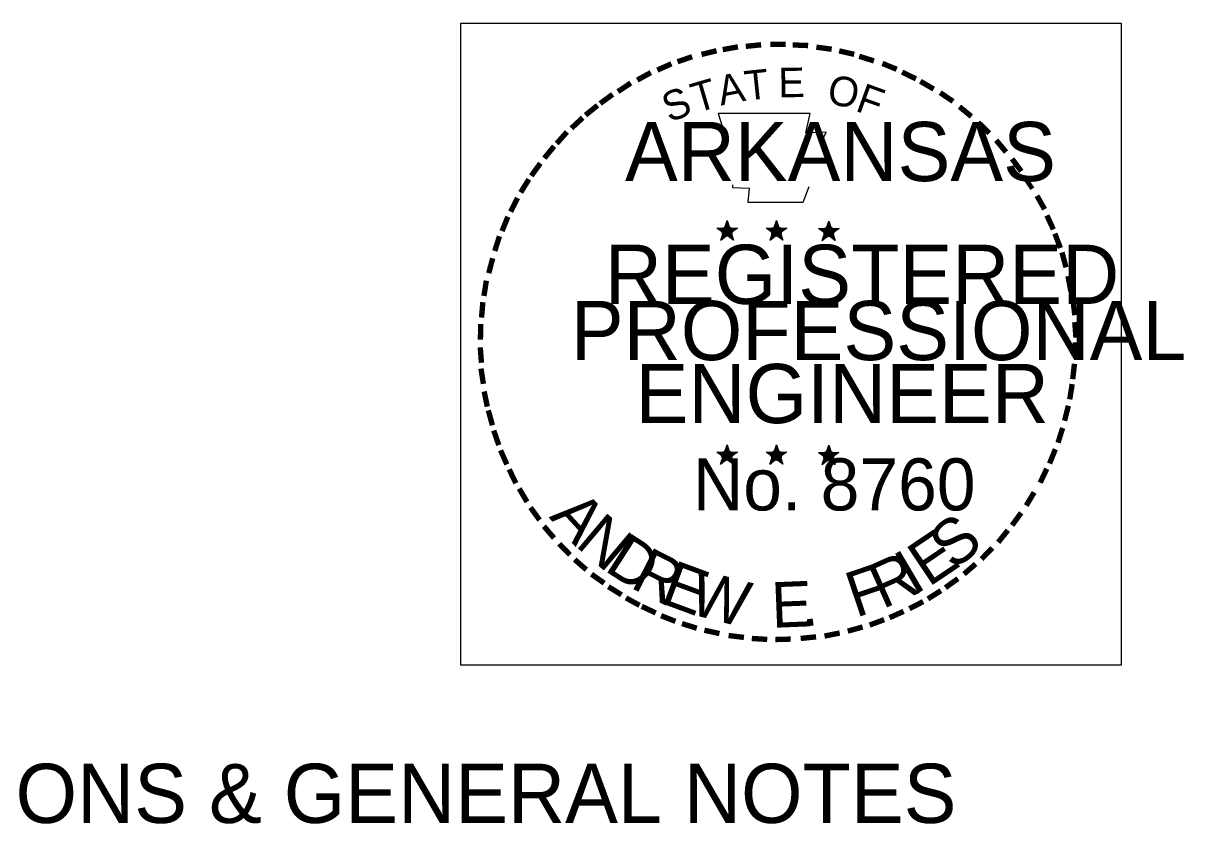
# Model space of a CAD drawing. Extents: x 1226673 to 1228148, y 151313 to 152324.
# Drawn here: x 1227902.7 to 1228147.9, y 151312.6 to 151481.8 of the extents above; entities that cross this region are included whole.
import ezdxf

# ---------------------------------------------------------------- set-up
doc = ezdxf.new("R2010")
doc.units = 0
for name, color, linetype in [('R_Border Notes', 7, 'Continuous'), ('R_Border PE', 7, 'Continuous'), ('R_Border Prem', 7, 'Continuous')]:
    doc.layers.add(name, color=color, linetype=linetype)

msp = doc.modelspace()

# ---------------------------------------------------------------- linework, layer by layer
at = {"layer": 'R_Border PE'}
for p, q in [((1228051.43, 151440.09), (1228051.11, 151438.53)), ((1228051.43, 151440.09), (1228051.18, 151438.47)), ((1228051.43, 151440.09), (1228051.36, 151438.53)), ((1228051.43, 151437.78), (1228051.43, 151440.09)), ((1228051.43, 151440.09), (1228051.86, 151438.47)), ((1228051.43, 151440.09), (1228051.74, 151438.53)), ((1228051.43, 151440.09), (1228051.61, 151438.53)), ((1228061.86, 151440.09), (1228061.55, 151438.53)), ((1228061.86, 151440.09), (1228061.61, 151438.47)), ((1228061.86, 151440.09), (1228061.74, 151438.53)), ((1228061.86, 151437.78), (1228061.86, 151440.09)), ((1228061.86, 151440.09), (1228062.3, 151438.47)), ((1228061.86, 151440.09), (1228062.18, 151438.53)), ((1228061.86, 151440.09), (1228061.99, 151438.53)), ((1228072.93, 151439.97), (1228072.55, 151438.47)), ((1228072.93, 151439.97), (1228072.68, 151438.41)), ((1228072.93, 151439.97), (1228072.8, 151438.41)), ((1228072.93, 151437.72), (1228072.93, 151439.97)), ((1228072.93, 151439.97), (1228073.36, 151438.41)), ((1228072.93, 151439.97), (1228073.24, 151438.41)), ((1228072.93, 151439.97), (1228073.05, 151438.47)), ((1228049.24, 151438.47), (1228051.43, 151437.78)), ((1228049.24, 151438.47), (1228050.86, 151438.34)), ((1228049.24, 151438.47), (1228050.86, 151438.22)), ((1228049.24, 151438.47), (1228050.8, 151438.09)), ((1228049.24, 151438.47), (1228050.8, 151437.84)), ((1228049.24, 151438.47), (1228050.74, 151437.72)), ((1228049.24, 151438.47), (1228050.74, 151437.59)), ((1228050.11, 151435.91), (1228051.43, 151437.78)), ((1228050.11, 151435.91), (1228050.8, 151437.66)), ((1228050.11, 151435.91), (1228050.86, 151437.47)), ((1228050.11, 151435.91), (1228050.99, 151437.41)), ((1228050.11, 151435.91), (1228051.43, 151437.28)), ((1228050.11, 151435.91), (1228051.18, 151437.22)), ((1228050.11, 151435.91), (1228051.49, 151437.09)), ((1228053.61, 151438.47), (1228051.43, 151437.78)), ((1228052.8, 151435.91), (1228051.43, 151437.78)), ((1228052.8, 151435.91), (1228051.43, 151437.28)), ((1228052.8, 151435.91), (1228051.43, 151437.09)), ((1228053.61, 151438.47), (1228051.68, 151438.34)), ((1228052.8, 151435.91), (1228051.68, 151437.22)), ((1228053.61, 151438.47), (1228051.8, 151438.16)), ((1228053.61, 151438.47), (1228051.8, 151438.03)), ((1228052.8, 151435.91), (1228051.86, 151437.47)), ((1228052.8, 151435.91), (1228051.93, 151437.72)), ((1228052.8, 151435.91), (1228052.05, 151437.78)), ((1228053.61, 151438.47), (1228052.24, 151437.91)), ((1228053.61, 151438.47), (1228052.36, 151437.84)), ((1228053.61, 151438.47), (1228052.43, 151437.78)), ((1228059.68, 151438.47), (1228061.86, 151437.78)), ((1228059.68, 151438.47), (1228061.3, 151438.34)), ((1228059.68, 151438.47), (1228061.3, 151438.22)), ((1228059.68, 151438.47), (1228061.24, 151438.09)), ((1228059.68, 151438.47), (1228061.18, 151437.84)), ((1228059.68, 151438.47), (1228061.18, 151437.72)), ((1228059.68, 151438.47), (1228061.18, 151437.59)), ((1228060.55, 151435.91), (1228061.86, 151437.78)), ((1228060.55, 151435.91), (1228061.24, 151437.66)), ((1228060.55, 151435.91), (1228061.3, 151437.47)), ((1228060.55, 151435.91), (1228061.43, 151437.41)), ((1228060.55, 151435.91), (1228061.86, 151437.28)), ((1228060.55, 151435.91), (1228061.61, 151437.22)), ((1228060.55, 151435.91), (1228061.93, 151437.09)), ((1228064.05, 151438.47), (1228061.86, 151437.78)), ((1228063.24, 151435.91), (1228061.86, 151437.78)), ((1228063.24, 151435.91), (1228061.86, 151437.28)), ((1228063.24, 151435.91), (1228061.86, 151437.09)), ((1228064.05, 151438.47), (1228062.11, 151438.34)), ((1228063.24, 151435.91), (1228062.11, 151437.22)), ((1228064.05, 151438.47), (1228062.24, 151438.16)), ((1228064.05, 151438.47), (1228062.24, 151438.03)), ((1228063.24, 151435.91), (1228062.3, 151437.47)), ((1228063.24, 151435.91), (1228062.36, 151437.72)), ((1228063.24, 151435.91), (1228062.49, 151437.78)), ((1228064.05, 151438.47), (1228062.68, 151437.91)), ((1228064.05, 151438.47), (1228062.8, 151437.84)), ((1228064.05, 151438.47), (1228062.86, 151437.78)), ((1228070.74, 151438.41), (1228072.93, 151437.72)), ((1228070.74, 151438.41), (1228072.36, 151438.22)), ((1228070.74, 151438.41), (1228072.3, 151438.09)), ((1228070.74, 151438.41), (1228072.3, 151438.03)), ((1228070.74, 151438.41), (1228072.24, 151437.78)), ((1228070.74, 151438.41), (1228072.24, 151437.66)), ((1228070.74, 151438.41), (1228072.24, 151437.53)), ((1228071.55, 151435.84), (1228072.93, 151437.72)), ((1228071.55, 151435.84), (1228072.3, 151437.59)), ((1228071.55, 151435.84), (1228072.36, 151437.41)), ((1228071.55, 151435.84), (1228072.49, 151437.34)), ((1228071.55, 151435.84), (1228072.93, 151437.22)), ((1228071.55, 151435.84), (1228072.68, 151437.16)), ((1228071.55, 151435.84), (1228072.99, 151437.03)), ((1228075.11, 151438.41), (1228072.93, 151437.72)), ((1228074.24, 151435.84), (1228072.93, 151437.72)), ((1228074.24, 151435.84), (1228072.93, 151437.22)), ((1228074.24, 151435.84), (1228072.93, 151437.03)), ((1228075.11, 151438.41), (1228073.18, 151438.28)), ((1228074.24, 151435.84), (1228073.18, 151437.16)), ((1228075.11, 151438.41), (1228073.3, 151438.09)), ((1228075.11, 151438.41), (1228073.3, 151437.97)), ((1228074.24, 151435.84), (1228073.36, 151437.41)), ((1228074.24, 151435.84), (1228073.43, 151437.66)), ((1228074.24, 151435.84), (1228073.55, 151437.66)), ((1228075.11, 151438.41), (1228073.74, 151437.84)), ((1228075.11, 151438.41), (1228073.8, 151437.78)), ((1228075.11, 151438.41), (1228073.93, 151437.72)), ((1228051.43, 151392.72), (1228051.05, 151391.22)), ((1228051.43, 151392.72), (1228051.18, 151391.16)), ((1228051.43, 151392.72), (1228051.3, 151391.16)), ((1228051.43, 151390.47), (1228051.43, 151392.72)), ((1228051.43, 151392.72), (1228051.86, 151391.16)), ((1228051.43, 151392.72), (1228051.74, 151391.16)), ((1228051.43, 151392.72), (1228051.55, 151391.16)), ((1228061.86, 151392.72), (1228061.49, 151391.22)), ((1228061.86, 151392.72), (1228061.61, 151391.16)), ((1228061.86, 151392.72), (1228061.74, 151391.16)), ((1228061.86, 151390.47), (1228061.86, 151392.72)), ((1228061.86, 151392.72), (1228062.24, 151391.16)), ((1228061.86, 151392.72), (1228062.18, 151391.16)), ((1228061.86, 151392.72), (1228061.99, 151391.16)), ((1228072.93, 151392.66), (1228072.55, 151391.09)), ((1228072.93, 151392.66), (1228072.68, 151391.09)), ((1228072.93, 151392.66), (1228072.8, 151391.09)), ((1228072.93, 151390.41), (1228072.93, 151392.66)), ((1228072.93, 151392.66), (1228073.3, 151391.09)), ((1228072.93, 151392.66), (1228073.24, 151391.09)), ((1228072.93, 151392.66), (1228073.05, 151391.09)), ((1228049.24, 151391.16), (1228051.43, 151390.47)), ((1228049.24, 151391.16), (1228050.86, 151390.97)), ((1228049.24, 151391.16), (1228050.8, 151390.84)), ((1228049.24, 151391.16), (1228050.8, 151390.78)), ((1228049.24, 151391.16), (1228050.74, 151390.53)), ((1228049.24, 151391.16), (1228050.74, 151390.41)), ((1228049.24, 151391.16), (1228050.74, 151390.28)), ((1228050.05, 151388.59), (1228051.43, 151390.47)), ((1228050.05, 151388.59), (1228050.8, 151390.34)), ((1228053.61, 151391.16), (1228051.43, 151390.47)), ((1228052.74, 151388.59), (1228051.43, 151390.47)), ((1228053.61, 151391.16), (1228051.68, 151391.03)), ((1228053.61, 151391.16), (1228051.8, 151390.84)), ((1228053.61, 151391.16), (1228051.8, 151390.72)), ((1228052.74, 151388.59), (1228051.86, 151390.41)), ((1228052.74, 151388.59), (1228052.05, 151390.41)), ((1228053.61, 151391.16), (1228052.18, 151390.59)), ((1228053.61, 151391.16), (1228052.3, 151390.53)), ((1228053.61, 151391.16), (1228052.43, 151390.41)), ((1228059.68, 151391.16), (1228061.86, 151390.47)), ((1228059.68, 151391.16), (1228061.24, 151390.97)), ((1228059.68, 151391.16), (1228061.24, 151390.84)), ((1228059.68, 151391.16), (1228061.24, 151390.78)), ((1228059.68, 151391.16), (1228061.18, 151390.53)), ((1228059.68, 151391.16), (1228061.18, 151390.41)), ((1228059.68, 151391.16), (1228061.18, 151390.28)), ((1228060.49, 151388.59), (1228061.86, 151390.47)), ((1228060.49, 151388.59), (1228061.24, 151390.34)), ((1228063.99, 151391.16), (1228061.86, 151390.47)), ((1228063.18, 151388.59), (1228061.86, 151390.47)), ((1228063.99, 151391.16), (1228062.11, 151391.03)), ((1228063.99, 151391.16), (1228062.24, 151390.84)), ((1228063.99, 151391.16), (1228062.24, 151390.72)), ((1228063.18, 151388.59), (1228062.3, 151390.41)), ((1228063.18, 151388.59), (1228062.49, 151390.41)), ((1228063.99, 151391.16), (1228062.61, 151390.59)), ((1228063.99, 151391.16), (1228062.74, 151390.53)), ((1228063.99, 151391.16), (1228062.86, 151390.41)), ((1228070.74, 151391.09), (1228072.93, 151390.41)), ((1228070.74, 151391.09), (1228072.3, 151390.91)), ((1228070.74, 151391.09), (1228072.3, 151390.78)), ((1228070.74, 151391.09), (1228072.24, 151390.66)), ((1228070.74, 151391.09), (1228072.24, 151390.47)), ((1228070.74, 151391.09), (1228072.18, 151390.28)), ((1228070.74, 151391.09), (1228072.18, 151390.16)), ((1228071.55, 151388.53), (1228072.93, 151390.41)), ((1228071.55, 151388.53), (1228072.24, 151390.28)), ((1228075.05, 151391.09), (1228072.93, 151390.41)), ((1228074.24, 151388.53), (1228072.93, 151390.41)), ((1228075.05, 151391.09), (1228073.18, 151390.97)), ((1228075.05, 151391.09), (1228073.3, 151390.78)), ((1228075.05, 151391.09), (1228073.3, 151390.66)), ((1228074.24, 151388.53), (1228073.36, 151390.34)), ((1228074.24, 151388.53), (1228073.49, 151390.34)), ((1228075.05, 151391.09), (1228073.68, 151390.53)), ((1228075.05, 151391.09), (1228073.8, 151390.41)), ((1228075.05, 151391.09), (1228073.86, 151390.34)), ((1228050.05, 151388.59), (1228050.86, 151390.09)), ((1228050.05, 151388.59), (1228050.99, 151390.03)), ((1228050.05, 151388.59), (1228051.43, 151389.97)), ((1228050.05, 151388.59), (1228051.18, 151389.91)), ((1228050.05, 151388.59), (1228051.43, 151389.78)), ((1228052.74, 151388.59), (1228051.36, 151389.78)), ((1228052.74, 151388.59), (1228051.43, 151389.91)), ((1228052.74, 151388.59), (1228051.61, 151389.91)), ((1228052.74, 151388.59), (1228051.86, 151390.16)), ((1228060.49, 151388.59), (1228061.3, 151390.09)), ((1228060.49, 151388.59), (1228061.43, 151390.03)), ((1228060.49, 151388.59), (1228061.86, 151389.97)), ((1228060.49, 151388.59), (1228061.61, 151389.91)), ((1228060.49, 151388.59), (1228061.86, 151389.78)), ((1228063.18, 151388.59), (1228061.8, 151389.78)), ((1228063.18, 151388.59), (1228061.86, 151389.91)), ((1228063.18, 151388.59), (1228062.05, 151389.91)), ((1228063.18, 151388.59), (1228062.3, 151390.16)), ((1228071.55, 151388.53), (1228072.3, 151390.03)), ((1228071.55, 151388.53), (1228072.49, 151389.97)), ((1228071.55, 151388.53), (1228072.68, 151389.84)), ((1228071.55, 151388.53), (1228072.86, 151389.84)), ((1228071.55, 151388.53), (1228072.93, 151389.72)), ((1228074.24, 151388.53), (1228072.86, 151389.84)), ((1228074.24, 151388.53), (1228072.86, 151389.66)), ((1228074.24, 151388.53), (1228073.11, 151389.84)), ((1228074.24, 151388.53), (1228073.3, 151390.03))]:
    msp.add_line(p, q, dxfattribs=at)
for points in [[(1228049.55, 151462.72), (1228051.18, 151457.53)], [(1228071.49, 151456.97), (1228072.36, 151458.72), (1228068.05, 151458.59), (1228068.99, 151462.72), (1228049.55, 151462.72)], [(1228052.61, 151447.59), (1228052.61, 151447.03), (1228056.11, 151446.91), (1228055.8, 151443.97), (1228067.49, 151443.97), (1228068.74, 151447.28)], [(1228051.43, 151440.09), (1228052.8, 151435.91), (1228049.24, 151438.47), (1228053.61, 151438.47), (1228050.11, 151435.91), (1228051.43, 151440.09)], [(1228061.86, 151440.09), (1228063.24, 151435.91), (1228059.68, 151438.47), (1228064.05, 151438.47), (1228060.55, 151435.91), (1228061.86, 151440.09)], [(1228072.93, 151439.97), (1228074.24, 151435.84), (1228070.74, 151438.41), (1228075.11, 151438.41), (1228071.55, 151435.84), (1228072.93, 151439.97)], [(1228051.43, 151392.72), (1228052.74, 151388.59), (1228049.24, 151391.16), (1228053.61, 151391.16), (1228050.05, 151388.59), (1228051.43, 151392.72)], [(1228061.86, 151392.72), (1228063.18, 151388.59), (1228059.68, 151391.16), (1228063.99, 151391.16), (1228060.49, 151388.59), (1228061.86, 151392.72)], [(1228072.93, 151392.66), (1228074.24, 151388.53), (1228070.74, 151391.09), (1228075.05, 151391.09), (1228071.55, 151388.53), (1228072.93, 151392.66)]]:
    msp.add_lwpolyline(points, dxfattribs=at)
for centre, radius in [((1228051.45, 151437.78), 1.08), ((1228051.45, 151437.78), 0.975), ((1228051.45, 151437.78), 0.904), ((1228051.45, 151437.78), 0.83), ((1228051.45, 151437.78), 0.723), ((1228051.45, 151437.78), 0.672), ((1228051.45, 151437.78), 0.619), ((1228051.45, 151437.78), 0.533), ((1228051.45, 151437.78), 0.467), ((1228051.45, 151437.78), 0.388), ((1228051.45, 151437.78), 0.31), ((1228051.45, 151437.78), 0.231), ((1228051.45, 151437.78), 0.185), ((1228051.45, 151437.78), 0.0901), ((1228061.88, 151437.78), 1.08), ((1228061.88, 151437.78), 0.975), ((1228061.88, 151437.78), 0.904), ((1228061.88, 151437.78), 0.83), ((1228061.88, 151437.78), 0.723), ((1228061.88, 151437.78), 0.672), ((1228061.88, 151437.78), 0.619), ((1228061.88, 151437.78), 0.533), ((1228061.88, 151437.78), 0.467), ((1228061.88, 151437.78), 0.388), ((1228061.88, 151437.78), 0.31), ((1228061.88, 151437.78), 0.231), ((1228061.88, 151437.78), 0.185), ((1228061.88, 151437.78), 0.0901), ((1228072.92, 151437.7), 1.08), ((1228072.92, 151437.7), 0.975), ((1228072.92, 151437.7), 0.904), ((1228072.92, 151437.7), 0.83), ((1228072.92, 151437.7), 0.723), ((1228072.92, 151437.7), 0.672), ((1228072.92, 151437.7), 0.619), ((1228072.92, 151437.7), 0.533), ((1228072.92, 151437.7), 0.467), ((1228072.92, 151437.7), 0.388), ((1228072.92, 151437.7), 0.31), ((1228072.92, 151437.7), 0.231), ((1228072.92, 151437.7), 0.185), ((1228072.92, 151437.7), 0.0901), ((1228051.42, 151390.45), 1.08), ((1228051.42, 151390.45), 0.975), ((1228051.42, 151390.45), 0.904), ((1228051.42, 151390.45), 0.83), ((1228051.42, 151390.45), 0.723), ((1228051.42, 151390.45), 0.672), ((1228051.42, 151390.45), 0.619), ((1228051.42, 151390.45), 0.533), ((1228051.42, 151390.45), 0.467), ((1228051.42, 151390.45), 0.388), ((1228051.42, 151390.45), 0.31), ((1228051.42, 151390.45), 0.231), ((1228051.42, 151390.45), 0.185), ((1228051.42, 151390.45), 0.0901), ((1228061.85, 151390.45), 1.08), ((1228061.85, 151390.45), 0.975), ((1228061.85, 151390.45), 0.904), ((1228061.85, 151390.45), 0.83), ((1228061.85, 151390.45), 0.723), ((1228061.85, 151390.45), 0.672), ((1228061.85, 151390.45), 0.619), ((1228061.85, 151390.45), 0.533), ((1228061.85, 151390.45), 0.467), ((1228061.85, 151390.45), 0.388), ((1228061.85, 151390.45), 0.31), ((1228061.85, 151390.45), 0.231), ((1228061.85, 151390.45), 0.185), ((1228061.85, 151390.45), 0.0901), ((1228072.9, 151390.37), 1.08), ((1228072.9, 151390.37), 0.975), ((1228072.9, 151390.37), 0.904), ((1228072.9, 151390.37), 0.83), ((1228072.9, 151390.37), 0.723), ((1228072.9, 151390.37), 0.672), ((1228072.9, 151390.37), 0.619), ((1228072.9, 151390.37), 0.533), ((1228072.9, 151390.37), 0.467), ((1228072.9, 151390.37), 0.388), ((1228072.9, 151390.37), 0.31), ((1228072.9, 151390.37), 0.231), ((1228072.9, 151390.37), 0.185), ((1228072.9, 151390.37), 0.0901)]:
    msp.add_circle(centre, radius, dxfattribs=at)
at = {"layer": 'R_Border Prem'}
msp.add_lwpolyline([(1227995.21, 151481.76), (1228134.71, 151481.76), (1228134.71, 151346.14), (1227995.21, 151346.14)], close=True, dxfattribs=at)

# ---------------------------------------------------------------- texts
at = {"layer": 'R_Border Notes'}
msp.add_text('GOVERNING SPECIFICATIONS & GENERAL NOTES ', height=12.5, dxfattribs=at).set_placement((1227691.22, 151312.82))
at = {"layer": 'R_Border PE'}
for s, height, rotation, p in [('-', 10, 13.6302, (1228046.36, 151471.28)), ('-', 10, 10.2193, (1228050.61, 151472.28)), ('-', 10, 5.8968, (1228055.18, 151472.97)), ('-', 10, 0.1862, (1228059.99, 151473.41)), ('-', 10, 357.743, (1228064.55, 151473.34)), ('-', 10, 352.1617, (1228069.18, 151472.97)), ('-', 10, 347.2049, (1228073.68, 151472.28)), ('-', 10, 24.3072, (1228037.74, 151468.09)), ('-', 10, 19.1761, (1228041.68, 151469.78)), ('-', 10, 342.3362, (1228077.61, 151471.28)), ('-', 10, 337.8551, (1228082.24, 151469.91)), ('-', 10, 28.7918, (1228033.8, 151466.09)), ('A', 6.25, 11.2132, (1228050.11, 151464.34)), ('T', 6.25, 6.0228, (1228055.43, 151465.41)), ('E', 6.25, 0.8323, (1228062.3, 151466.09)), ('-', 10, 334.1211, (1228086.18, 151468.22)), ('-', 10, 34.0636, (1228030.05, 151463.78)), ('T', 6.25, 16.4036, (1228044.93, 151462.78)), ('O', 6.25, 350.4515, (1228072.36, 151464.78)), ('F', 6.25, 340.0707, (1228078.3, 151463.34)), ('-', 10, 329.6409, (1228089.8, 151466.47)), ('-', 10, 36.2317, (1228026.43, 151461.34)), ('S', 6.25, 21.594, (1228039.24, 151460.72)), ('-', 10, 325.8627, (1228093.8, 151464.22)), ('-', 10, 38.9507, (1228023.49, 151458.97)), ('-', 10, 320.5297, (1228097.61, 151461.53)), ('-', 10, 42.9622, (1228020.74, 151456.34)), ('-', 10, 48.423, (1228017.93, 151453.34)), ('-', 10, 315.5786, (1228101.36, 151458.47)), ('-', 10, 309.8797, (1228104.93, 151455.03)), ('-', 10, 50.6142, (1228015.43, 151450.34)), ('-', 10, 54.2325, (1228012.86, 151446.78)), ('-', 10, 306.6522, (1228108.18, 151451.28)), ('-', 10, 58.0706, (1228010.8, 151443.47)), ('-', 8.75, 303.6753, (1228111.24, 151447.72)), ('-', 10, 62.8713, (1228008.86, 151439.66)), ('-', 10, 299.6684, (1228113.24, 151443.91)), ('-', 10, 67.7743, (1228007.24, 151435.84)), ('-', 10, 294.6628, (1228115.24, 151440.09)), ('-', 10, 72.3945, (1228005.86, 151431.91)), ('-', 10, 290.5728, (1228116.86, 151436.53)), ('-', 10, 75.461, (1228004.68, 151427.41)), ('-', 10, 285.1233, (1228118.3, 151432.91)), ('-', 10, 81.2013, (1228003.8, 151422.97)), ('-', 10, 280.5493, (1228119.55, 151428.22)), ('-', 10, 85.1863, (1228003.36, 151418.66)), ('-', 10, 276.5962, (1228120.61, 151423.47)), ('-', 10, 89.0622, (1228003.18, 151414.28)), ('-', 10, 274.3301, (1228120.99, 151418.91)), ('-', 10, 94.1959, (1228003.43, 151409.72)), ('-', 10, 269.9407, (1228121.18, 151414.97)), ('-', 10, 263.5172, (1228121.05, 151410.84)), ('-', 10, 98.9479, (1228003.86, 151405.59)), ('-', 10, 260.9953, (1228120.61, 151406.72)), ('-', 10, 101.7149, (1228004.68, 151400.97)), ('-', 10, 105.4578, (1228005.74, 151397.28)), ('-', 10, 255.7626, (1228119.93, 151402.47)), ('-', 10, 109.0874, (1228007.05, 151393.34)), ('-', 10, 252.8681, (1228118.8, 151397.97)), ('-', 10, 114.0643, (1228008.68, 151389.59)), ('-', 10, 247.8887, (1228117.43, 151393.78)), ('-', 10, 115.7289, (1228010.55, 151385.72)), ('-', 10, 244.6197, (1228115.74, 151389.84)), ('-', 10, 120.4471, (1228012.8, 151382.09)), ('-', 10, 239.0712, (1228113.3, 151385.16)), ('A', 9.62, 312.4727, (1228013.68, 151377.4)), ('-', 10, 125.8934, (1228015.3, 151378.59)), ('N', 9.62, 319.8362, (1228019.11, 151371.47)), ('-', 10, 233.8452, (1228110.8, 151381.09)), ('-', 10, 130.7181, (1228018.18, 151375.09)), ('S', 9.62, 39.723, (1228099.34, 151366)), ('D', 9.62, 327.1996, (1228025.26, 151366.28)), ('E', 9.62, 33.8878, (1228094, 151362.52)), ('-', 10, 231.2538, (1228108.11, 151377.53)), ('-', 10, 134.2238, (1228021.43, 151371.72)), ('R', 9.62, 333.1738, (1228030.7, 151362.68)), ('-', 10, 225.7653, (1228105.11, 151374.03)), ('-', 10, 138.9338, (1228024.68, 151368.84)), ('R', 9.62, 24.0235, (1228084.27, 151357.92)), ('I', 9.62, 30.5534, (1228090.8, 151360.78)), ('-', 10, 144.6463, (1228028.18, 151366.28)), ('E', 9.62, 339.7037, (1228037.04, 151359.41)), ('W', 9.62, 345.5389, (1228042.99, 151357.12)), ('F', 9.62, 18.6051, (1228078.62, 151356.13)), ('-', 10, 221.0851, (1228101.86, 151370.84)), ('-', 10, 148.0898, (1228031.68, 151363.97)), ('E', 9.62, 2.2804, (1228060.96, 151354.03)), ('-', 10, 215.7363, (1228098.43, 151367.91)), ('-', 10, 151.5704, (1228035.3, 151361.91)), ('-', 10, 212.2491, (1228095.05, 151365.47)), ('-', 10, 154.6002, (1228038.55, 151360.41)), ('-', 10, 207.3568, (1228091.61, 151363.28)), ('-', 10, 158.5612, (1228042.49, 151358.78)), ('.', 9.62, 8.1156, (1228067.34, 151354.2)), ('-', 10, 200.7184, (1228083.8, 151359.59)), ('-', 10, 204.2516, (1228087.68, 151361.28)), ('-', 10, 162.7983, (1228046.74, 151357.47)), ('-', 10, 167.5555, (1228051.24, 151356.47)), ('-', 10, 191.2858, (1228075.05, 151356.84)), ('-', 10, 195.4743, (1228079.61, 151358.09)), ('-', 10, 173.1155, (1228056.05, 151355.78)), ('-', 10, 176.5183, (1228060.74, 151355.41)), ('-', 10, 181.5918, (1228065.36, 151355.53)), ('-', 10, 185.8167, (1228070.43, 151356.03))]:
    msp.add_text(s, height=height, rotation=rotation, dxfattribs=at).set_placement(p)
for s, height, p in [('ARKANSAS', 12.5, (1228029.86, 151448.41)), ('REGISTERED', 12.5, (1228025.61, 151422.47)), ('PROFESSIONAL', 12.4999, (1228018.43, 151410.59)), ('ENGINEER', 12.5, (1228032.11, 151397.28)), ('No. 8760', 11, (1228044.22, 151378.84))]:
    msp.add_text(s, height=height, dxfattribs=at).set_placement(p)

doc.saveas('drawing.dxf')
